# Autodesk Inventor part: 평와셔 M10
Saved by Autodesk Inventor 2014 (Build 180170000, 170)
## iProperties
Created: 2024-08
Part Number: 평와셔 M10
Material: 일반
Document SubType Name: Modeling
Designer: dg
Density: 1 g/cm^3
Appearance: 기본값
Author: dg
Author: jhkim
Description: 평면 와셔
Creation Date: 2024-08-09
Sending System: Autodesk Inventor 2025
Preprocessor: ST-DEVELOPER v20
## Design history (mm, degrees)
node "평와셔 M101"
body "Solid1"
node "기준1"
